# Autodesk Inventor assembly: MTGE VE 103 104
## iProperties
Shininess: 41.0
Angle Display Precision: 2
Document Length Units: 11269
Document Angle Units: 11279
Document Time Units: 11290
Document Mass Units: 11283
Document Length Units Precision: 3
Document Angle Units Precision: 2
Part Number: MTGE VE 103 104
Document SubType Name: Assembly
Density: 0.0
Volumn: 0.0
Area: 0.0
PropertySet Name: Model Information
Control State: 0
Master: False
Checked Out: False
